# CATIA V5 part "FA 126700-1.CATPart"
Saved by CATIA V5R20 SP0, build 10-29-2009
Part number: FA 126700-1
Revision: ANY
Definition: UNKNOWN
Nomenclature: FA 126700-1
Source: Unknown
Bounding box of the stored display mesh (mm): x -3.804 to 3.804, y 0.2 to 2.5, z -4 to 4
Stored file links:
  C:\Users\Utente\Desktop\IO LAVORO\3D X SITO CF\CUMSA\3D files FA\FA 1267SF\FA 126700-1.CATPart

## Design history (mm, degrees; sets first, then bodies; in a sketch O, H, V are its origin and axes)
Body1 "Cortar-Extruir1" (main body)
  Solid1: solid without history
